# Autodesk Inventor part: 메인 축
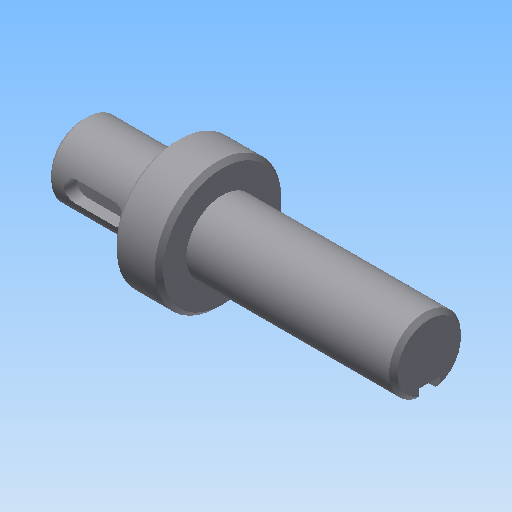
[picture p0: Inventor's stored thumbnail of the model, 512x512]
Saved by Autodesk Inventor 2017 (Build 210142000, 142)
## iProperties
Created: 2014-10
Part Number: 메인 축
Document SubType Name: Modeling
Designer: KYOUNG IL JANG
Density: 7.86 g/cm^3
Mass: 230.24 g
Surface Area: 74.3518 cm^2
Volume: 29.2926 cm^3
Material: 강철, 연강
Appearance: 금속-강(스테인리스, 브러시됨)
Author: SeoGD™ [www.esajin.kr]
Revision Number: 1
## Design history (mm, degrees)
sketch "스케치1"
  geometry: L1 (10.497, -57.5)-(92.497, -57.5); L2 (10.497, -66)-(32.497, -66); L3 (32.497, -72.5)-(46.5, -72.5); L4 (46.5, -66)-(92.497, -66); L5 (92.497, -66)-(92.497, -57.5); L6 (10.497, -66)-(10.497, -57.5); L7 (46.5, -69.749)-(46.5, -45.251) reference; L8 (46.5, -72.5)-(46.5, -66); L9 (32.497, -72.5)-(32.497, -66); L10 (32.497, -35)-(32.497, -80) reference; 2 further points
  constraints: 16 end point, 2 parallel, 2 perpendicular, 2 point on line, 1 collinear, 1 horizontal, 1 midpoint
  dimensions: "d0" = 17 diameter of L4 L1; "d1" = 30 diameter of L3 L1; "d2" = 22 distance of L2.start L2.end; "d5" = 17 diameter of L2 L1; "d19" = 60 distance between parallel lines of L5 L9
revolve "회전1" sketch "스케치1" stored, may be unused: angle "d4" = 90 deg
feature "면 이동2"
chamfer "모따기1" distance "d6" = 1; stored, may be unused: second distance "d7" = 2, angle "d8" = 45 deg
node "작업 평면1"
sketch "스케치2"
  geometry: L1 (-11, -7.5)-(-11, 7.5) reference; L2 (-4.5, 2.5)-(4.5, 2.5); L3 (4.5, -2.5)-(-4.5, -2.5); A1 r 2.5 centre (4.5, 0) between (4.5, -2.5) and (4.5, 2.5); A2 r 2.5 centre (-4.5, 0) between (-4.5, 2.5) and (-4.5, -2.5); 2 further points
  constraints: 4 end point, 4 point on circle, 4 tangent, 2 centre point, 1 horizontal alignment, 1 midpoint, 1 parallel, 1 perpendicular
  dimensions: "d9" = 5 distance between parallel lines of L3 L2; "d10" = 14 dimension on A1 A2; "d11" = 4 distance edge to line of A2 L1
extrude "돌출1" cut sketch "스케치2" distance "d12" = 3; taper "d13" = 0 deg
node "작업 평면2"
sketch "스케치3"
  geometry: L1 (22.998, 7.5)-(22.998, -7.5) reference; L2 (22.998, 2.5)-(7.498, 2.5); L3 (7.498, -2.5)-(22.998, -2.5); A1 r 2.5 centre (7.498, 0) between (7.498, 2.5) and (7.498, -2.5); 2 further points
  constraints: 4 end point, 2 perpendicular, 2 point on circle, 2 point on line, 2 tangent, 1 centre point, 1 horizontal alignment, 1 midpoint
  dimensions: "d14" = 5 distance between parallel lines of L3 L2; "d15" = 18 dimension on A1 L1
extrude "돌출2" cut sketch "스케치3" distance "d16" = 3; taper "d17" = 0 deg
node "솔리드1"
node "참조4"
node "참조5"
